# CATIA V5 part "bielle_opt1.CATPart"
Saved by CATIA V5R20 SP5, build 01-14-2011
Part number: Part1
Bounding box of the stored display mesh (mm): x 0 to 5, y -5 to 65, z -5 to 5
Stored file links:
  U:\IAO\Part1.CATPart
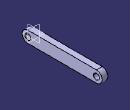
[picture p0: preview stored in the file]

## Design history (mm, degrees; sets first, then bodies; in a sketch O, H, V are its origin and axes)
Body1 (main body)
  Sketch1 on yz-plane, origin (0, 0, 0), H (0, 1, 0), V (0, 0, 1)
    circle A1 centre (0, 0) radius 2.5
    circle A2 centre (60, 0) radius 2.5
    point P1 (60, 0)
    construction line L1 (0, 0) -> (60, 0)
    line L2 (0, 5) -> (60, 5)
    line L3 (60, -5) -> (0, -5)
    arc A3 centre (60, 0) radius 5 from (60, 5) to (60, -5) cw
    arc A4 centre (0, 0) radius 5 from (0, -5) to (0, 5) cw
    radius A1 = 2.5
    radius A2 = 2.5
    distance P1 O = 60
    distance L1 L2 = 5
    horizontal: L1 H
    tangency: A3 L2, A4 L2, A3 L3, A4 L3
  Pad1: profile Sketch1, direction (1, 0, 0), length 5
